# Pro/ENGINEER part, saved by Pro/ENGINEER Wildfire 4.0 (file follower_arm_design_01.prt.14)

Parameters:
  METRIC = "NO"

Other parameters: PITCH, DRILL_DIAMETER, THREAD_DIAMETER, THREADS_PER_INCH, THREAD_DEPTH, THREAD_LENGTH, DRILL_POINT_ANGLE, DRILL_DEPTH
